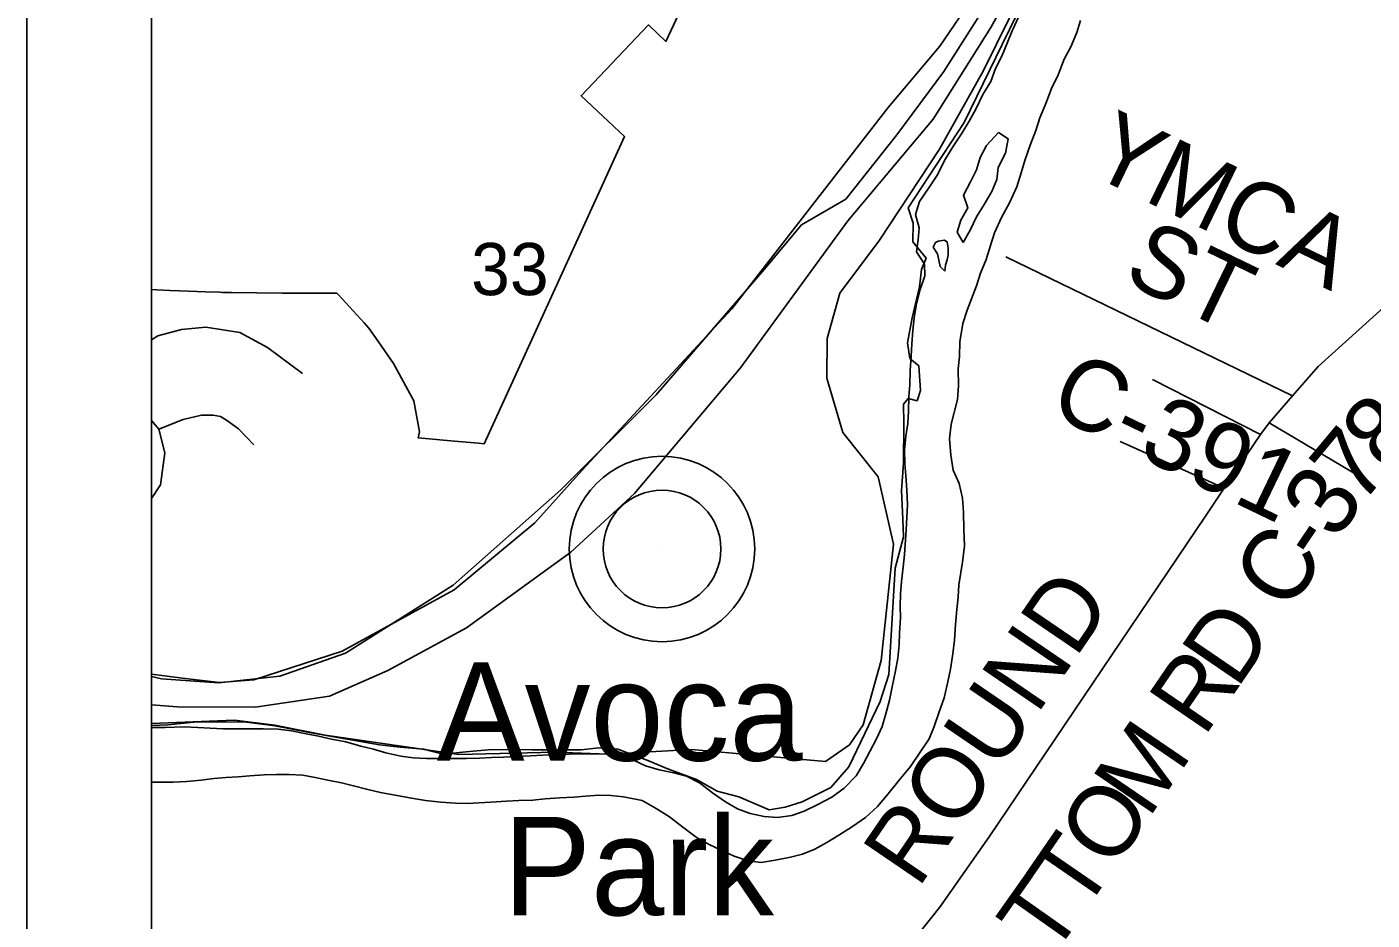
# Model space of a CAD drawing. Extents: x 44.2 to 78.2, y 4.5 to 26.5.
# Drawn here: x 46.236 to 47.315, y 19.208 to 19.924 of the extents above; entities that cross this region are included whole.
import ezdxf

# ---------------------------------------------------------------- set-up
doc = ezdxf.new("R2010")
doc.units = 0
for name, color, linetype in [('GM_X_County_Road', 7, 'Continuous'), ('GM_X_County_Road_Text', 7, 'Continuous'), ('GM_X_Interstate_Route', 7, 'Continuous'), ('GM_X_Major_River', 7, 'Continuous'), ('GM_X_Rail_Line', 7, 'Continuous'), ('GM_X_Section_Text', 7, 'Continuous'), ('GM_X_State_Shield', 7, 'Continuous'), ('GM_X_Township_Road', 7, 'Continuous'), ('GM_X_Unincorporated', 7, 'Continuous'), ('GM_X_Unincorporated_Location', 7, 'Continuous'), ('GM_X_Unincorporated_Text', 7, 'Continuous'), ('GM_X_US_Route', 7, 'Continuous'), ('SH_Cut_Line', 7, 'Continuous'), ('SH_Data', 7, 'Continuous')]:
    doc.layers.add(name, color=color, linetype=linetype)

msp = doc.modelspace()

# ---------------------------------------------------------------- linework, layer by layer
at = {"layer": 'GM_X_County_Road'}
for p, q in [((47.2513, 19.6284), (47.0212, 19.7399)), ((46.8686, 19.0931), (46.9639, 19.2128))]:
    msp.add_line(p, q, dxfattribs=at)
msp.add_lwpolyline([(46.9639, 19.2128), (46.9687, 19.2188), (47.0077, 19.2745), (47.1813, 19.5318), (47.1963, 19.5543), (47.2256, 19.5974), (47.2325, 19.6068), (47.2513, 19.6284), (47.2717, 19.6519), (47.3595, 19.7311)], dxfattribs=at)
at = {"layer": 'GM_X_Interstate_Route'}
msp.add_lwpolyline([(46.3359, 23.204), (46.3359, 19.7136), (46.34, 19.7134), (46.3506, 19.713), (46.3584, 19.7127), (46.3791, 19.7119), (46.3903, 19.7115), (46.3925, 19.7114), (46.4001, 19.7114), (46.4204, 19.7111), (46.4406, 19.7108), (46.445, 19.7108), (46.4738, 19.7107), (46.4845, 19.7107), (46.4858, 19.7093), (46.5064, 19.6869), (46.5102, 19.6826), (46.5178, 19.6718), (46.53, 19.6542), (46.5464, 19.6245), (46.5507, 19.5994), (46.5497, 19.5948), (46.5528, 19.5945), (46.579, 19.5921), (46.5981, 19.5903), (46.6027, 19.5899), (46.6313, 19.6525), (46.6864, 19.7731), (46.7154, 19.8364), (46.6804, 19.8691), (46.7346, 19.926), (46.7485, 19.9127), (46.7665, 19.9517)], dxfattribs=at)
at = {"layer": 'GM_X_Major_River'}
for points in [[(47.0315, 19.9328), (47.0262, 19.9212), (47.0222, 19.9114), (47.0181, 19.9009), (47.0129, 19.8911), (47.0091, 19.8806), (47.0028, 19.8701), (46.9971, 19.8585), (46.9919, 19.8487), (46.9856, 19.8386), (46.9788, 19.8282), (46.9721, 19.8173), (46.9664, 19.8057), (46.9593, 19.7952), (46.9518, 19.7844), (46.9488, 19.7738), (46.9516, 19.7631), (46.9509, 19.7536), (46.9495, 19.7438), (46.956, 19.7341), (46.9561, 19.7246), (46.9524, 19.7137), (46.9494, 19.7023), (46.9476, 19.691), (46.9466, 19.6807), (46.9459, 19.6701), (46.9452, 19.6602), (46.9445, 19.6488), (46.9442, 19.6371), (46.9435, 19.6276), (46.9432, 19.6162), (46.9425, 19.6063), (46.9411, 19.5961), (46.94, 19.5847), (46.9401, 19.574), (46.941, 19.5645), (46.9418, 19.5527), (46.9422, 19.5413), (46.9419, 19.531), (46.9413, 19.5208), (46.9399, 19.501), (46.9389, 19.4908), (46.9374, 19.4794)], [(46.976, 19.594), (46.9774, 19.6057), (46.9825, 19.6254), (46.9832, 19.6364), (46.9829, 19.6501), (46.9839, 19.6599), (46.9842, 19.6717), (46.9866, 19.6865), (46.9903, 19.697), (46.9977, 19.7166), (47.001, 19.7268), (47.0055, 19.7377), (47.0088, 19.749), (47.0121, 19.7592), (47.0178, 19.7716), (47.0242, 19.7832), (47.0299, 19.796), (47.0336, 19.8073), (47.0365, 19.8171), (47.0407, 19.8295), (47.0452, 19.8412), (47.0485, 19.8514), (47.0534, 19.863), (47.0579, 19.8751), (47.0632, 19.886), (47.0681, 19.8984), (47.0733, 19.9085), (47.0782, 19.9198), (47.0811, 19.9296)], [(47.0152, 19.8397), (47.0058, 19.8293), (47.0006, 19.8196), (46.9976, 19.8098), (46.9928, 19.8), (46.9872, 19.7895), (46.9907, 19.7792), (46.9851, 19.7694), (46.9822, 19.7596), (46.9869, 19.7515)], [(46.9869, 19.7515), (46.9925, 19.7612), (46.9977, 19.7721), (47.0037, 19.7819), (47.01, 19.7923), (47.0141, 19.8021), (47.0151, 19.8116), (47.0208, 19.8232), (47.023, 19.8346), (47.0152, 19.8397)], [(46.9649, 19.7513), (46.9629, 19.7476), (46.9665, 19.7422), (46.9675, 19.7372), (46.9685, 19.7322), (46.9722, 19.7283)], [(46.9722, 19.7283), (46.9727, 19.7333), (46.974, 19.7374), (46.9748, 19.7416), (46.975, 19.7469), (46.974, 19.7519), (46.9718, 19.7534), (46.9668, 19.7524), (46.9649, 19.7513)], [(46.3359, 19.3183), (46.3433, 19.3183), (46.3532, 19.3184), (46.3638, 19.3189), (46.3756, 19.3201), (46.3859, 19.3213), (46.3954, 19.3222), (46.4053, 19.3227), (46.4148, 19.3236), (46.4262, 19.3244), (46.436, 19.3245), (46.4463, 19.3246), (46.4573, 19.324), (46.4671, 19.3222), (46.4773, 19.32), (46.4882, 19.3178), (46.498, 19.3156), (46.5082, 19.3127), (46.5195, 19.3101), (46.5444, 19.3056), (46.5557, 19.3038), (46.5678, 19.3023), (46.5796, 19.3016), (46.589, 19.3014), (46.608, 19.3024), (46.6206, 19.3032), (46.6305, 19.3037), (46.6418, 19.3041), (46.6517, 19.305), (46.6631, 19.3058), (46.6745, 19.3063), (46.684, 19.3072), (46.6947, 19.308), (46.7042, 19.3078), (46.7144, 19.3067), (46.7295, 19.3037), (46.7407, 19.2973), (46.7515, 19.2905), (46.7622, 19.2822), (46.7738, 19.2736), (46.7838, 19.268), (46.8033, 19.2591), (46.8146, 19.2554), (46.8248, 19.2539), (46.8362, 19.2559), (46.8484, 19.2582), (46.858, 19.2606), (46.868, 19.2646), (46.8776, 19.27), (46.8872, 19.2758), (46.8981, 19.2828), (46.9085, 19.2901), (46.9183, 19.2989), (46.9269, 19.309), (46.9355, 19.3201), (46.9446, 19.3309), (46.9596, 19.3533), (46.9637, 19.3631), (46.9674, 19.374), (46.9716, 19.3861), (46.9746, 19.3989), (46.9768, 19.4092), (46.9786, 19.4213), (46.9801, 19.4323), (46.9808, 19.4448), (46.9819, 19.4569), (46.983, 19.4668), (46.9836, 19.4767), (46.9864, 19.4948), (46.9879, 19.5081), (46.9876, 19.5214), (46.9872, 19.5351), (46.9864, 19.5462), (46.9837, 19.558), (46.979, 19.5688), (46.9771, 19.5807), (46.976, 19.594)], [(46.9374, 19.4794), (46.9368, 19.4696), (46.9365, 19.4597), (46.9366, 19.4502), (46.9359, 19.438), (46.9356, 19.4285), (46.9345, 19.4179), (46.9327, 19.4077), (46.9301, 19.3948), (46.9279, 19.3842), (46.9249, 19.3733), (46.922, 19.3631), (46.9175, 19.3533), (46.9123, 19.3436), (46.9071, 19.3335), (46.9011, 19.3234), (46.8914, 19.3137), (46.8817, 19.3064), (46.8705, 19.3006), (46.8593, 19.2952), (46.8494, 19.2917), (46.838, 19.2901), (46.8274, 19.2908), (46.816, 19.2933), (46.8059, 19.297), (46.7962, 19.3026), (46.7858, 19.3098), (46.7754, 19.318), (46.7649, 19.3232), (46.7548, 19.3258), (46.7431, 19.3284), (46.7321, 19.3314), (46.722, 19.3362), (46.7123, 19.3387), (46.7009, 19.3409), (46.6907, 19.3412), (46.6812, 19.3411), (46.671, 19.341), (46.6607, 19.3405), (46.6497, 19.3401), (46.6398, 19.3396), (46.628, 19.3391), (46.6185, 19.3386), (46.6087, 19.3381), (46.5992, 19.3376), (46.5885, 19.3375), (46.5764, 19.3375), (46.5662, 19.3374), (46.5563, 19.3373), (46.5457, 19.3379), (46.5359, 19.3393), (46.5238, 19.3419), (46.514, 19.3449), (46.5038, 19.3474), (46.4918, 19.3508), (46.4801, 19.353), (46.4699, 19.3552), (46.4586, 19.3574), (46.448, 19.3596), (46.4375, 19.361), (46.4257, 19.3613), (46.4136, 19.3613), (46.4029, 19.3612), (46.3931, 19.3611), (46.3829, 19.3617), (46.373, 19.3624), (46.362, 19.3627), (46.3468, 19.3623), (46.337, 19.3622), (46.3359, 19.3621)]]:
    msp.add_lwpolyline(points, dxfattribs=at)
at = {"layer": 'GM_X_Rail_Line'}
for points in [[(46.3359, 23.0552), (46.3359, 19.3655), (46.4023, 19.3682), (46.4348, 19.3641), (46.4752, 19.356), (46.5825, 19.3405), (46.6593, 19.3426), (46.7022, 19.3409), (46.7691, 19.3445), (46.8766, 19.335), (46.8957, 19.3485), (46.9068, 19.3645), (46.9213, 19.416), (46.9311, 19.5095), (46.9188, 19.5635), (46.8903, 19.5989), (46.8776, 19.6426), (46.8778, 19.6745), (46.8881, 19.7107), (46.9198, 19.7533), (46.968, 19.8263), (47.0034, 19.8893), (47.0343, 19.9525)], [(46.3359, 19.3805), (46.3568, 19.3788), (46.419, 19.3787), (46.4785, 19.3873), (46.5255, 19.408), (46.5884, 19.4423), (46.6721, 19.5029), (46.7232, 19.5499), (46.8082, 19.6509), (46.8945, 19.7688), (46.963, 19.8504), (47.0092, 19.9238), (47.0354, 19.9715), (47.0632, 20.0175), (47.1027, 20.0588), (47.1461, 20.0932), (47.2154, 20.1327), (47.284, 20.1605), (47.4563, 20.2277), (47.5349, 20.2612), (47.6148, 20.3025), (47.6612, 20.3309), (47.7346, 20.388)], [(47.7346, 20.388), (47.6541, 20.3502), (47.5813, 20.3179), (47.2745, 20.1805), (47.2067, 20.1517), (47.1389, 20.111), (47.0792, 20.063), (47.029, 20.0084), (47.0219, 19.9787), (47.0127, 19.9537), (46.9715, 19.8885), (46.9338, 19.8379), (46.8928, 19.7862), (46.8574, 19.7657), (46.8274, 19.7297), (46.7408, 19.6293), (46.6642, 19.5529), (46.5778, 19.4766), (46.4914, 19.422), (46.4387, 19.4034), (46.3898, 19.3982), (46.3438, 19.4014), (46.3359, 19.4031)], [(47.0343, 19.9525), (47.0034, 19.8893), (46.968, 19.8263), (46.9198, 19.7533), (46.8881, 19.7107), (46.8778, 19.6745), (46.8776, 19.6426), (46.8903, 19.5989), (46.9188, 19.5635), (46.9311, 19.5095), (46.9213, 19.416), (46.9068, 19.3645), (46.8957, 19.3485), (46.8766, 19.335), (46.7691, 19.3445), (46.7022, 19.3409), (46.6593, 19.3426), (46.5825, 19.3405), (46.4752, 19.356), (46.4348, 19.3641), (46.4023, 19.3682), (46.3359, 19.3655), (46.3359, 18.6014), (48.642, 18.6014)]]:
    msp.add_lwpolyline(points, dxfattribs=at)
at = {"layer": 'GM_X_State_Shield'}
msp.add_lwpolyline([(46.3359, 19.9803), (46.3359, 19.3638), (46.3365, 19.3638), (46.349, 19.3643), (46.3725, 19.3668), (46.388, 19.3665), (46.41, 19.3668), (46.435, 19.3637), (46.461, 19.3586), (46.4867, 19.3539), (46.5187, 19.3484), (46.5354, 19.3465), (46.5543, 19.345), (46.5697, 19.3409), (46.591, 19.3431), (46.6058, 19.3444), (46.6198, 19.3445), (46.641, 19.3444), (46.6804, 19.3444), (46.6948, 19.346), (46.7099, 19.3449), (46.734, 19.3357), (46.7505, 19.3289), (46.7731, 19.3205), (46.7895, 19.3111), (46.8069, 19.3066), (46.8313, 19.2963), (46.8442, 19.2983), (46.8579, 19.3026), (46.8809, 19.3142), (46.8952, 19.3306), (46.9205, 19.3831), (46.9274, 19.4049), (46.9325, 19.49), (46.9391, 19.5153), (46.9385, 19.5295), (46.9376, 19.5524), (46.9391, 19.5744), (46.9394, 19.6062), (46.939, 19.6217), (46.9428, 19.6262), (46.95, 19.6245), (46.9528, 19.6328), (46.9513, 19.6525), (46.9442, 19.6584), (46.9422, 19.6709), (46.946, 19.6909), (46.9518, 19.7158), (46.9536, 19.7298), (46.9572, 19.7388), (46.9465, 19.7519), (46.9468, 19.767), (46.9429, 19.7792), (46.9878, 19.8476), (47.0182, 19.9103), (47.0356, 19.9459)], dxfattribs=at)
at = {"layer": 'GM_X_Township_Road'}
for p, q in [((47.2256, 19.5974), (47.1389, 19.6416)), ((47.2325, 19.6068), (47.3131, 19.5588)), ((47.1963, 19.5543), (47.1129, 19.5918))]:
    msp.add_line(p, q, dxfattribs=at)
for points in [[(46.3359, 19.6732), (46.3409, 19.6764), (46.3598, 19.6816), (46.3793, 19.6834), (46.4066, 19.6792), (46.4289, 19.6673), (46.4569, 19.6463)], [(46.3359, 19.6085), (46.3416, 19.6016), (46.3465, 19.5827), (46.343, 19.5569), (46.3359, 19.5459)], [(46.3416, 19.6016), (46.3612, 19.6093), (46.3758, 19.6128), (46.3853, 19.6128), (46.3911, 19.6117), (46.3961, 19.6089), (46.4055, 19.602), (46.4178, 19.589)]]:
    msp.add_lwpolyline(points, dxfattribs=at)
at = {"layer": 'GM_X_Unincorporated'}
for radius in [0.0744, 0.0472]:
    msp.add_circle((46.7454, 19.5055), radius, dxfattribs=at)
at = {"layer": 'GM_X_Unincorporated_Location'}
msp.add_line((46.7454, 19.5055), (46.7454, 19.5055), dxfattribs=at)
at = {"layer": 'GM_X_US_Route'}
msp.add_lwpolyline([(46.3359, 19.4051), (46.3629, 19.4017), (46.3904, 19.3985), (46.4178, 19.4006), (46.4887, 19.4236), (46.5787, 19.4727), (46.6434, 19.5264), (46.6814, 19.5687), (46.8013, 19.6982), (46.9269, 19.8598), (46.9682, 19.9089), (46.9837, 19.9317), (46.9948, 19.9575), (47.0182, 19.996), (47.0409, 20.0257), (47.072, 20.0581), (47.1084, 20.0907), (47.1235, 20.1021), (47.1653, 20.1253), (47.2333, 20.1613), (47.3477, 20.2122)], dxfattribs=at)
at = {"layer": 'SH_Cut_Line'}
msp.add_lwpolyline([(46.3359, 25.4014), (46.3359, 18.6014), (48.642, 18.6014), (48.8628, 20.3534), (48.8669, 20.386), (48.8687, 20.4006), (48.8692, 20.405), (48.8786, 20.4919), (48.8828, 20.7853), (48.9071, 20.9822), (48.9653, 21.1731), (49.0288, 21.2696), (49.1258, 21.308)], dxfattribs=at)
at = {"layer": 'SH_Data'}
for p, q in [((46.2359, 25.5014), (46.2359, 18.5014)), ((46.3359, 25.4014), (46.3359, 18.6014))]:
    msp.add_line(p, q, dxfattribs=at)

# ---------------------------------------------------------------- texts
at = {"layer": 'GM_X_County_Road_Text'}
for s, height, rotation, p in [('YMCA', 0.05682, 334.152, (47.085, 19.8078)), ('ST', 0.05682, 334.2303, (47.1137, 19.7208)), ('C-391', 0.05682, 334.2993, (47.0536, 19.6152)), ('8', 0.0568, 46.6708, (47.327, 19.5652)), ('7', 0.0568, 50.1235, (47.3052, 19.539)), ('3', 0.0568, 55.9794, (47.2865, 19.5112)), ('-', 0.0568, 56.0523, (47.2735, 19.4919)), ('C', 0.0568, 56.061, (47.2474, 19.4532)), ('ROUND', 0.05682, 55.6785, (46.9508, 19.2323)), ('D', 0.0568, 55.6995, (47.2065, 19.3923)), ('R', 0.0568, 55.6969, (47.1802, 19.3538)), ('M', 0.0568, 55.7013, (47.1356, 19.2884)), ('O', 0.0568, 55.6693, (47.1073, 19.247)), ('T', 0.0568, 55.4761, (47.0831, 19.2119)), ('T', 0.0568, 54.8068, (47.0582, 19.1765))]:
    msp.add_text(s, height=height, rotation=rotation, dxfattribs=at).set_placement(p)
at = {"layer": 'GM_X_Section_Text'}
msp.add_text('33', height=0.04186, rotation=0, dxfattribs=at).set_placement((46.5922, 19.7092))
at = {"layer": 'GM_X_Unincorporated_Text'}
for s, p in [('Avoca', (46.5647, 19.3357)), ('Park', (46.618, 19.2116))]:
    msp.add_text(s, height=0.07898, rotation=0, dxfattribs=at).set_placement(p)

doc.saveas('drawing.dxf')
